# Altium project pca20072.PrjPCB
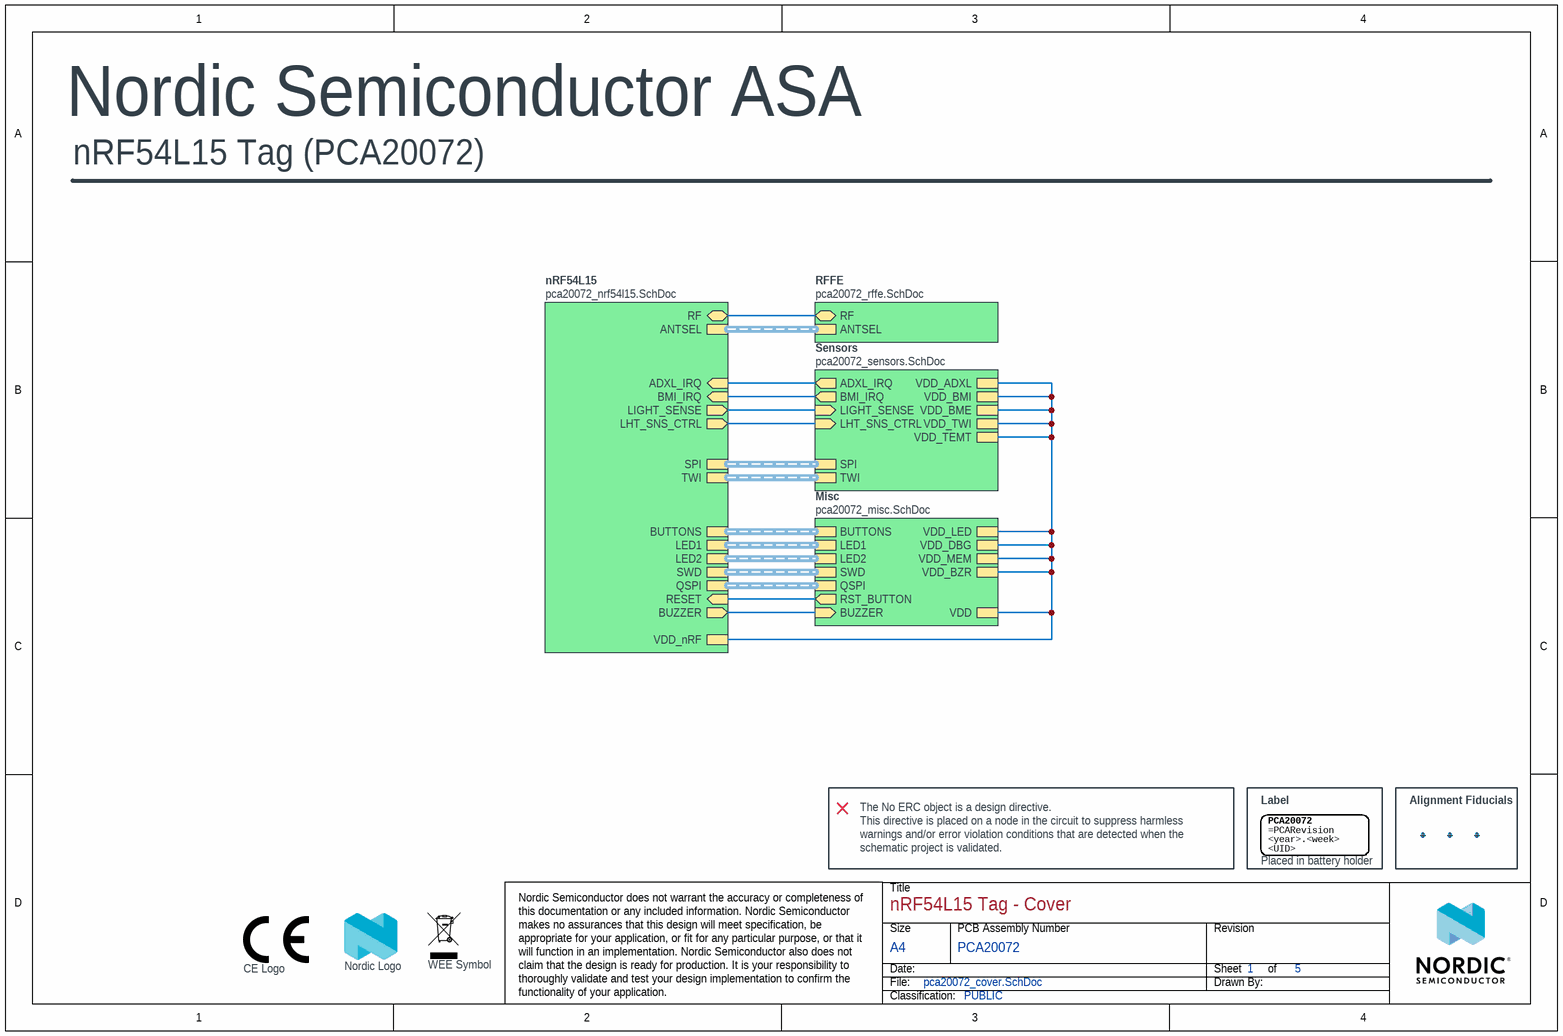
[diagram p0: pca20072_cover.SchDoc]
BoardThickness: 0.8mm; BoardTitle: nRF54L15 Tag; Classification: PUBLIC; Compliance: RoHS, REACH, Halogen-Free; Designer: RUBR; Dielectric: FR-4; NrOfLayers: 4; Organization: Nordic Semiconductor; PCAName: PCA20072; PCARevision: 1.0.0; PCBNumber: 400921; PCBRevision: 0491RUBR; PCBStackup: 4003; ProductName: nRF54L15-TAG; ProjectName: nRF54L15-TAG; SilkscreenColor: White; SoldermaskColor: Blue; SurfaceFinish: ENIG Gold
5 sheets, 113 parts. Net scope: hierarchical (ports join the sheet entries above them; power ports are global).
Board file: 400921.PcbDoc
Sheets:
  pca20072_cover.SchDoc
    nRF54L15 = pca20072_nrf54l15.SchDoc
    RFFE = pca20072_rffe.SchDoc
    Sensors = pca20072_sensors.SchDoc
    Misc = pca20072_misc.SchDoc

## Sheet pca20072_cover.SchDoc: nRF54L15 Tag - Cover
size A4; Organization: Nordic Semiconductor; DocumentNumber: 1; Revision: 1.0.0; SheetNumber: 1; SheetTotal: 5; Author: RUBR; CompanyName: Nordic Semiconductor; DrawnBy: RUBR; DocumentSize: A4

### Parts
Fid1  Fiducial mark  [Fiducial]  (value not drawn)
Fid2  Fiducial mark  [Fiducial]  (value not drawn)
Fid3  Fiducial mark  [Fiducial]  (value not drawn)
LABEL1  Assembly: Placed in battery holder  [LabelSilk_8x8]  (hidden comment: 8x8mm)
LOGO1  WEE Symbol  [WEEE_3x4.5mm]  (no BOM)
LOGO2  Nordic Logo  [NORDIC_LOGO_LYING]  (no BOM)
LOGO3  CE Logo  [CE_logo]  (no BOM)

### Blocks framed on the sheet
Label: LABEL1
Alignment Fiducials: Fid1-Fid3

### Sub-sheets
Misc = pca20072_misc.SchDoc: BUTTONS (harness BUTTON), QSPI (harness QSPI), LED1 (harness LED), SWD (harness SWD), VDD_MEM, VDD_LED, VDD_DBG, LED2 (harness LED), BUZZER (in), VDD_BZR, RST_BUTTON (out), VDD
nRF54L15 = pca20072_nrf54l15.SchDoc: BUTTONS (harness BUTTON), LED1 (harness LED), SWD (harness SWD), RESET (in), RF (bidir), ANTSEL (harness ANT), QSPI (harness QSPI), ADXL_IRQ (in), BMI_IRQ (in), SPI (harness SPI), TWI (harness TWI), VDD_nRF, LHT_SNS_CTRL (out), LED2 (harness LED), LIGHT_SENSE (out), BUZZER (out)
RFFE = pca20072_rffe.SchDoc: RF (bidir), ANTSEL (harness ANT)
Sensors = pca20072_sensors.SchDoc: ADXL_IRQ (out), BMI_IRQ (out), SPI (harness SPI), TWI (harness TWI), VDD_BMI, VDD_ADXL, VDD_BME, VDD_TWI, LIGHT_SENSE (in), LHT_SNS_CTRL (in), VDD_TEMT

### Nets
P0.03: sheet nRF54L15/ADXL_IRQ, sheet Sensors/ADXL_IRQ
P1.04: sheet nRF54L15/BMI_IRQ, sheet Sensors/BMI_IRQ
P1.13: sheet nRF54L15/BUZZER, sheet Misc/BUZZER
P1.14: sheet nRF54L15/LIGHT_SENSE, sheet Sensors/LIGHT_SENSE
P2.06: sheet nRF54L15/LHT_SNS_CTRL, sheet Sensors/LHT_SNS_CTRL
RESET: sheet nRF54L15/RESET, sheet Misc/RST_BUTTON
RF: sheet nRF54L15/RF, sheet RFFE/RF
VDD: sheet nRF54L15/VDD_nRF, sheet Sensors/VDD_BMI, sheet Sensors/VDD_ADXL, sheet Sensors/VDD_BME, sheet Sensors/VDD_TWI, sheet Sensors/VDD_TEMT, sheet Misc/VDD_MEM, sheet Misc/VDD_LED, sheet Misc/VDD_DBG, sheet Misc/VDD_BZR, sheet Misc/VDD

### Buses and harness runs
harness sheet Misc/BUTTONS = sheet nRF54L15/BUTTONS
harness sheet Misc/LED1 = sheet nRF54L15/LED1
harness sheet Misc/LED2 = sheet nRF54L15/LED2
harness sheet Misc/QSPI = sheet nRF54L15/QSPI
harness sheet Misc/SWD = sheet nRF54L15/SWD
harness sheet nRF54L15/ANTSEL = sheet RFFE/ANTSEL
harness sheet nRF54L15/SPI = sheet Sensors/SPI
harness sheet nRF54L15/TWI = sheet Sensors/TWI

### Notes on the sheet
- (near LABEL1) The No ERC object is a design directive.
  This directive is placed on a node in the circuit to suppress harmless warnings and/or error violation conditions that are detected when the schematic project is validated.

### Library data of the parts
Fid1-Fid3 = Fid-Mark: Manufacturer: N.A.; Part number NEMS: 100500073; Value: N.A.; Pad Count: 1; Component Status: Active; System: Connector
LABEL1 = Label_8x8: PCA version label, stick-on, 8x8mm; Manufacturer: Ellco Etikett; Manufacturer Part Number: A33511-01; Part number NEMS: 101200025; Component Status: Active; Pad Count: 0; Note: N.A.
LOGO1 = WEEE Symbol 3x4.5mm: WEEE Directive symbol; Manufacturer: N.A.; Part number NEMS: 101100006; Component Status: Active; Pad Count: 0
LOGO2 = Nordic Logo lying: Manufacturer: N.A.; Part number NEMS: 101100001; Component Status: Active; Pad Count: 0
LOGO3 = CE_logo: CE (Conformité_Européenne) logo; Manufacturer: N.A.; Part number NEMS: 101100010; Component Status: Active; Pad Count: 0

## Sheet pca20072_nrf54l15.SchDoc: =BoardTitle+' - nRF54L15'
size A4; Organization: Nordic Semiconductor; DocumentNumber: 2; Revision: 1.0.0; SheetNumber: 2; SheetTotal: 5; Author: RUBR; CompanyName: Nordic Semiconductor; DrawnBy: RUBR; DocumentSize: A4
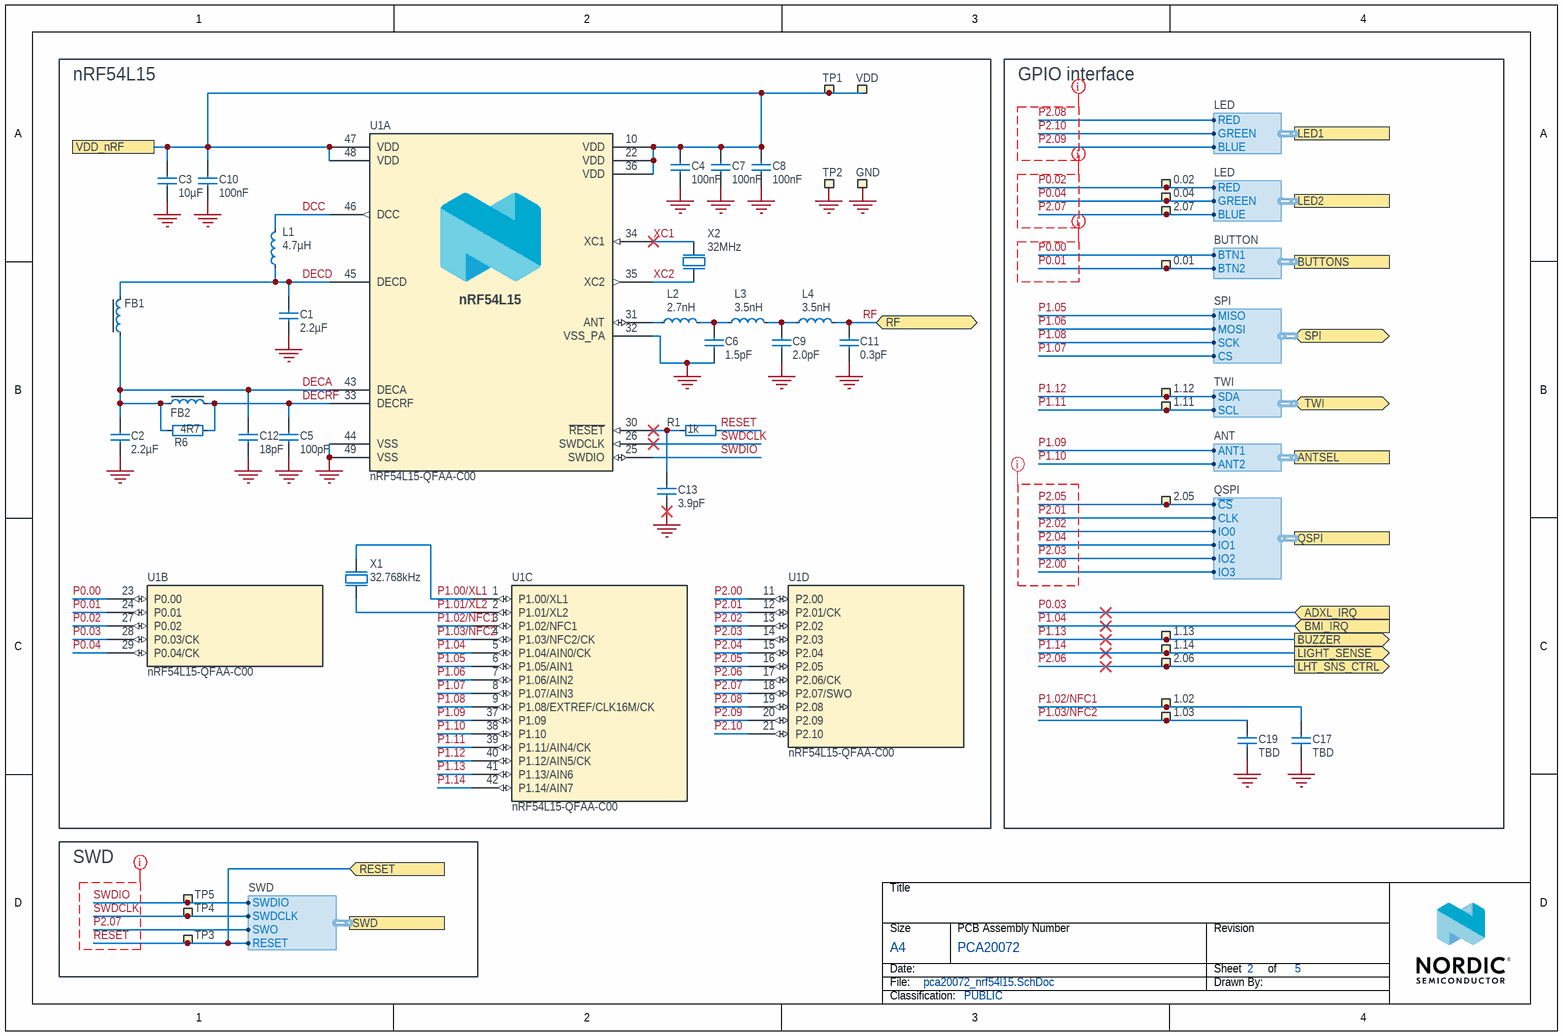
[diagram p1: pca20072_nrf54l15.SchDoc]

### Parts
0.01  TP  [TESTPAD-TH]  (value not drawn)  (no BOM)
0.02  TP  [TESTPAD-TH]  (value not drawn)  (no BOM)
0.04  TP  [TESTPAD-TH]  (value not drawn)  (no BOM)
1.02  TP  [TESTPAD-TH]  (value not drawn)  (no BOM)
1.03  TP  [TESTPAD-TH]  (value not drawn)  (no BOM)
1.11  TP  [TESTPAD-TH]  (value not drawn)  (no BOM)
1.12  TP  [TESTPAD-TH]  (value not drawn)  (no BOM)
1.13  TP  [TESTPAD-TH]  (value not drawn)  (no BOM)
1.14  TP  [TESTPAD-TH]  (value not drawn)  (no BOM)
2.05  TP  [TESTPAD-TH]  (value not drawn)  (no BOM)
2.06  TP  [TESTPAD-TH]  (value not drawn)  (no BOM)
2.07  TP  [TESTPAD-TH]  (value not drawn)  (no BOM)
C1  2.2µF  [CAPC0603X03L_C]
C2  2.2µF  [CAPC0603X03L_C]
C3  10µF  [CAPC1005X04L_C2]
C4  100nF  [CAPC0603X03L_C]
C5  100pF  [CAPC0603X03L_C]
C6  1.5pF  [CAPC0603X03L_C]
C7  100nF  [CAPC0603X03L_C]
C8  100nF  [CAPC0603X03L_C]
C9  2.0pF  [CAPC0603X03L_C]
C10  100nF  [CAPC0603X03L_C]
C11  0.3pF  [CAPC0603X03L_C]
C12  18pF  [CAPC0603X03L_C]
C13  3.9pF  [CAPC0603X03L_C]
C17  TBD  [CAPC1005X04L]
C19  TBD  [CAPC1005X04L]
FB1  120R/0.2A  [INDC0603X03L_C]  (value not drawn)
FB2  120R/0.2A  [INDC0603X03L_C]  (value not drawn)
GND  TP  [TESTPAD-TH]  (value not drawn)  (no BOM)
L1  4.7µH  [INDC1608X06L]
L2  2.7nH  [INDC0603X03L_C]
L3  3.5nH  [INDC0603X03L_C]
L4  3.5nH  [INDC0603X03L_C]
R1  1k  [RESC0603X03L_C]
R6  4R7  [RESC0603X03L_C]
TP1  Ø1.5mm,SMD  [TP_SMD_D1.5mm]  (value not drawn)  (no BOM)
TP2  Ø1.5mm,SMD  [TP_SMD_D1.5mm]  (value not drawn)  (no BOM)
TP3  Ø1.5mm,SMD  [TP_SMD_D1.5mm]  (value not drawn)  (no BOM)
TP4  Ø1.5mm,SMD  [TP_SMD_D1.5mm]  (value not drawn)  (no BOM)
TP5  Ø1.5mm,SMD  [TP_SMD_D1.5mm]  (value not drawn)  (no BOM)
U1  nRF54L15-QFAA-C00  [QFN40P600X600X90-48N]  (parts A,B,C,D of 4)
VDD  TP  [TESTPAD-TH]  (value not drawn)  (no BOM)
X1  32.768kHz  [XTAL_2012]
X2  32MHz  [BT-XTAL_2016]

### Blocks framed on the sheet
nRF54L15: C1-C13 FB1 FB2 GND L1-L4 R1 R6 TP1 TP2 U1 VDD X1 X2
GPIO interface: 0.01 0.02 0.04 1.02 1.03 1.11-1.14 2.05 2.06 2.07 C17 C19
SWD: TP3-TP5

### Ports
ADXL_IRQ (in), ANTSEL (harness ANT), BMI_IRQ (in), BUTTONS (harness BUTTON), BUZZER (out), LED1 (harness LED), LED2 (harness LED), LHT_SNS_CTRL (out), LIGHT_SENSE (out), QSPI (harness QSPI), RESET (in), RF (bidir), SPI (bidir, harness SPI), SWD (harness SWD), TWI (bidir, harness TWI), VDD_nRF

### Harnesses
SWD: SWDIO, SWDCLK, SWO, RESET
LED: GREEN, RED, BLUE
BUTTON: BTN2, BTN1
ANT: ANT2, ANT1
QSPI: ~{CS}, IO0, CLK, IO1, IO2, IO3
SPI: MISO, MOSI, SCK, CS
TWI: SCL, SDA

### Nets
GND: C1.1 C2.1 C3.1 C4.2 C5.1 C6.1 C7.2 C8.2 C9.1 C10.2 C11.1 C12.1 C13.1 C17.2 C19.2 GND.1 TP2.1 U1.32(VSS_PA) U1.44(VSS) U1.49(VSS) X2.2(GND) X2.4(GND)
DCC: L1.1 U1.46(DCC)
DECA: C2.2 C12.2 FB1.2 FB2.2 R6.2 U1.43(DECA)
DECD: C1.2 FB1.1 L1.2 U1.45(DECD)
DECRF: C5.2 FB2.1 R6.1 U1.33(DECRF)
P0.00: U1.23(P0.00) ; port BUTTONS.BTN1
P0.01: 0.01.1 U1.24(P0.01) ; port BUTTONS.BTN2
P0.02: 0.02.1 U1.27(P0.02) ; port LED2.RED
P0.03: U1.28(P0.03/CK) ; port ADXL_IRQ
P0.04: 0.04.1 U1.29(P0.04/CK) ; port LED2.GREEN
P1.00/XL1: U1.1(P1.00/XL1) X1.2(out)
P1.01/XL2: U1.2(P1.01/XL2) X1.1(inp)
P1.02/NFC1: 1.02.1 C17.1 U1.3(P1.02/NFC1)
P1.03/NFC2: 1.03.1 C19.1 U1.4(P1.03/NFC2/CK)
P1.04: U1.5(P1.04/AIN0/CK) ; port BMI_IRQ
P1.05: U1.6(P1.05/AIN1) ; port SPI.MISO
P1.06: U1.7(P1.06/AIN2) ; port SPI.MOSI
P1.07: U1.8(P1.07/AIN3) ; port SPI.CS
P1.08: U1.9(P1.08/EXTREF/CLK16M/CK) ; port SPI.SCK
P1.09: U1.37(P1.09) ; port ANTSEL.ANT1
P1.10: U1.38(P1.10) ; port ANTSEL.ANT2
P1.11: 1.11.1 U1.39(P1.11/AIN4/CK) ; port TWI.SCL
P1.12: 1.12.1 U1.40(P1.12/AIN5/CK) ; port TWI.SDA
P1.13: 1.13.1 U1.41(P1.13/AIN6) ; port BUZZER
P1.14: 1.14.1 U1.42(P1.14/AIN7) ; port LIGHT_SENSE
P2.00: U1.11(P2.00) ; port QSPI.IO3
P2.01: U1.12(P2.01/CK) ; port QSPI.CLK
P2.02: U1.13(P2.02) ; port QSPI.IO0
P2.03: U1.14(P2.03) ; port QSPI.IO2
P2.04: U1.15(P2.04) ; port QSPI.IO1
P2.05: 2.05.1 U1.16(P2.05) ; port QSPI.~{CS}
P2.06: 2.06.1 U1.17(P2.06/CK) ; port LHT_SNS_CTRL
P2.07: 2.07.1 U1.18(P2.07/SWO) ; port SWD.SWO, port LED2.BLUE
P2.08: U1.19(P2.08) ; port LED1.RED
P2.09: U1.20(P2.09) ; port LED1.BLUE
P2.10: U1.21(P2.10) ; port LED1.GREEN
RESET: R1.2 TP3.1 ; port RESET, port SWD.RESET
RF: C11.2 L4.2 ; port RF
SWDCLK: TP4.1 U1.26(SWDCLK) ; port SWD.SWDCLK
SWDIO: TP5.1 U1.25(SWDIO) ; port SWD.SWDIO
VDD: C3.2 C4.1 C7.1 C8.1 C10.1 TP1.1 U1.10(VDD) U1.22(VDD) U1.36(VDD) U1.47(VDD) U1.48(VDD) VDD.1 ; port VDD_nRF
XC1: U1.34(XC1) X2.1(inp)
XC2: U1.35(XC2) X2.3(out)
NetC6_2: C6.2 L2.2 L3.1
NetC9_2: C9.2 L3.2 L4.1
NetC13_2: C13.2 R1.1 U1.30(~{RESET})
NetL2_1: L2.1 U1.31(ANT)

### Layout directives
net class GPIO: P0.00, P0.01, P0.02, P0.04, P2.07, P2.08, P2.09, P2.10
net class SWD_nRF54: P2.07, RESET, SWDCLK, SWDIO
net class QSPI: P2.00, P2.01, P2.02, P2.03, P2.04, P2.05

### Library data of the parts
0.01 0.02 0.04 1.02 1.03 1.11-1.14 2.05 2.06 2.07 GND VDD = Testpoint TH: Testpoint, through hole; Manufacturer: N.A.; Part number NEMS: 100500464; Component Status: Active; Pad Count: 1
C1 C2 = C0201-2µ2-2.5V-X6T-GRM033D80E225ME47D: Capacitor, Ceramic, 2.2µF 2.5V X6T 0201,±20%; Manufacturer: Murata; Part number NEMS: 100200527; Component Status: Active; Pad Count: 2; Note: 2.5V, 20%, X6T; Artikkelnr Noca: N.A.
C3 = C0402-10µ-6.3V-X5R-GRM155R60J106ME05D: Capacitor, X5R, ±20%, 6.3V; Manufacturer: Murata; Part number NEMS: 100200554; Component Status: Active; Pad Count: 2; Artikkelnr Noca: N.A.
C4 C7 C8 C10 = C0201-100n: Capacitor, X5R, ±10%, 100nF, 16V; Manufacturer: N.A.; Part number IPS: 00000001248, 00000002505; Part number Norautron: 262071862; Part number NEMS: 100200078; Pad Count: 2; Component Status: Active
C5 = C0201-100p: Capacitor, NP0, ±2%, 25V; Manufacturer: Murata; Manufacturer Part Number: GRM0335C1E101GA01D; Part number IPS: 00000007853; Part number NEMS: 100200044; Component Status: Active; Pad Count: 2; Artikkelnr Noca: N.A.
C6 = C0201-1.5p-25V-NP0-GJM0335C1E1R5WB01: Capacitor, NP0, ±0.05pF, 25V, High Q; Manufacturer: Murata; Part number NEMS: 100200477; Component Status: Active; Pad Count: 2; Artikkelnr Noca: N.A.
C9 = C0201-2.0p-HQ-Murata: Capacitor, NP0, ±0.05pF, 25V; Manufacturer: Murata; Manufacturer Part Number: GJM0335C1E2R0WB01; Part number IPS: 00000001775; Part number NEMS: 100200419; Component Status: Active; Pad Count: 2; Artikkelnr Noca: N.A.
C11 = C0201-0.3p-50V-GRM0335C1HR30BA01: Capacitor, C0G, ±0.1pF, 50V; Manufacturer: Murata; Part number NEMS: 100200650; Component Status: Active; Pad Count: 2; Artikkelnr Noca: N.A.
C12 = C0201-18p: Capacitor, C0G, ±5%, 25V; Manufacturer: Walsin Technology Corporation; Manufacturer Part Number: 0201N180J250CT; Part number IPS: 00000000862; Part number Norautron: 26207023; Part number NEMS: 100200035; Component Status: Active; Pad Count: 2; Note: Chip Cap 5%; Artikkelnr Noca: N.A.
C13 = C0201-3.9p: Chip Cap 0201; Manufacturer: N.A.; Part number NEMS: 100200024,100200424; Component Status: Active; Pad Count: 2; Note: Chip Cap 1%
C17 C19 = C0402-TBD: Chip Cap 0402; Manufacturer: N.A.; Part number NEMS: 100200106; Pad Count: 2; Component Status: Active
FB1 FB2 = FB0201-120R@100M-200mA-BLM03AG121SN1D: Ferrite Bead, 120 Ohm @ 100MHz, 200mA, 500 mOhm Max; Manufacturer: Murata; Part number NEMS: 100300419; Component Status: Active; Pad Count: 2; Artikkelnr Noca: N.A.
L1 = L0603-4µ7-MLZ1608M4R7WT000: Inductor, 120mA, ±20%, 0.65R; Manufacturer: TDK Corporation; Part number NEMS: 100300440; Component Status: Active; Pad Count: 2; Note: Power Inductor ±20%; Artikkelnr Noca: N.A.
L2 = L0201-2n7-HQ-Murata: Inductor, 600mA, ±0.1ｎH, 120mOhm; Manufacturer: Murata; Manufacturer Part Number: LQP03HQ2N7B02; Part number IPS: 00000001753; Part number NEMS: 100300214; Component Status: Active; Pad Count: 2; Note: -55°C ~ 125°C; Artikkelnr Noca: N.A.
L3 L4 = L0201-3n5-HQ-Murata: Inductor, 500mA, ±0.1ｎH, 170mOhm; Manufacturer: Murata; Manufacturer Part Number: LQP03HQ3N5B02; Part number NEMS: 100300222; Component Status: Active; Pad Count: 2; Note: -55°C ~ 125°C; Artikkelnr Noca: N.A.
R1 = R0201-1k0: Resistor, ±1%, 0.05W; Manufacturer: N.A.; Part number IPS: 00000005786; Part number NEMS: 100100043; Component Status: Active; Pad Count: 2; Note: Chip Res 1%
R6 = R0201-4R7: Resistor, ±1%, 0.05W; Manufacturer: N.A.; Part number IPS: 00000002486; Part number NEMS: 100100010; Component Status: Active; Pad Count: 2; Note: Chip Res 1%
TP1-TP5 = TP_SMD_Ø1.5MM: 1.5mm circular SMD testpad; Manufacturer: Nordic Semiconductor; Manufacturer Part Number: N.A.; Part number NEMS: 100500477; Component Status: Active; Pad Count: 1
U1 = nRF54L15-QFAA-C00: Multi-protocol Bluetooth Low Energy, IEEE 802.15.4 and 2.4GHz proprietary Wireless MCU; Manufacturer: Nordic Semiconductor; Part number NEMS: 102000382; Component Status: Active; Pad Count: 49; Note: N.A.
X1 = XTAL_SMD2012_32.768kHz_9pF_TXC: XTAL SMD 2012, 32.768kHz, 9pF, ±20ppm; Manufacturer: TXC Corporation; Manufacturer Part Number: 9HT11-32.768KDZC-T; Part number NEMS: 101600107; Component Status: Active; Pad Count: 2; Note: XTAL SMD 32.768kHz; Artikkelnr Noca: N.A.
X2 = XTAL_SMD2016_32MHz_8pF_Kyocera: XTAL SMD 2016, 32MHz, Cl=8pF, Tot: ±40ppm; Manufacturer Part Number: CX2016DB32000D0WZRC1; Part number IPS: 00000007827; Part number Norautron: 26511136; Part number NEMS: 101600039; Component Status: Active; Pad Count: 4; Note: XTAL SMD 32.000MHz; Artikkelnr Noca: 22010022

## Sheet pca20072_rffe.SchDoc: nRF54L15 Tag - RFFE
size A4; Organization: Nordic Semiconductor; DocumentNumber: 3; Revision: 1.0.0; SheetNumber: 3; SheetTotal: 5; Author: RUBR; CompanyName: Nordic Semiconductor; DrawnBy: RUBR; DocumentSize: A4
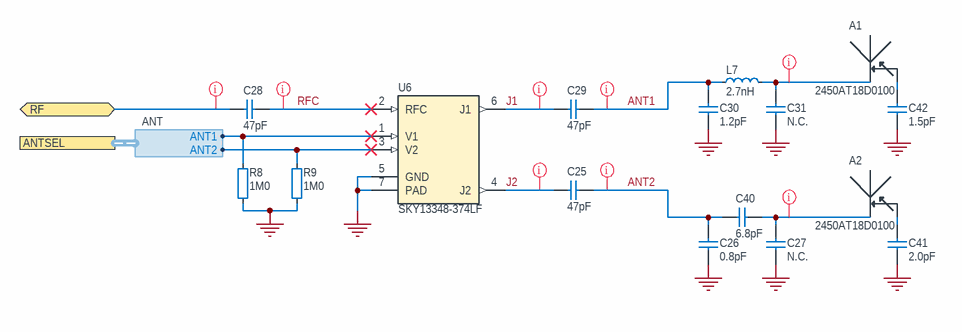
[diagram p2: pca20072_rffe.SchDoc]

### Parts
A1  2450AT18D0100  [2450AT18D0100_TE-R]
A2  2450AT18D0100  [2450AT18D0100_TE-L]
C25  47pF  [CAPC0603X03L_C]
C26  0.8pF  [CAPC1005X04L_C2]
C27  N.C.  [CAPC1005X04L_C2]
C28  47pF  [CAPC0603X03L_C]
C29  47pF  [CAPC0603X03L_C]
C30  1.2pF  [CAPC1005X04L_C2]
C31  N.C.  [CAPC1005X04L_C2]
C40  6.8pF  [CAPC1005X04L_C2]
C41  2.0pF  [CAPC1005X04L_C2]
C42  1.5pF  [CAPC1005X04L_C2]
L7  2.7nH  [INDC1005X04L_C2]
R8  1M0  [RESC0603X03L_C]
R9  1M0  [RESC0603X03L_C]
U6  SKY13348-374LF  [SON50P150X50_HS-7N]

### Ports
ANTSEL (harness ANT), RF (bidir)

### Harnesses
ANT: ANT2, ANT1

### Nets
GND: A1.2(GND) A2.2(GND) C26.1 C27.1 C30.1 C31.1 C41.1 C42.1 R8.1 R9.1 U6.5(GND) U6.7(PAD)
ANT1: C29.1 C30.2 L7.1
ANT2: C25.1 C26.2 C40.1
J1: C29.2 U6.6(J1)
J2: C25.2 U6.4(J2)
P1.09: R8.2 U6.1(V1) ; port ANTSEL.ANT1
P1.10: R9.2 U6.3(V2) ; port ANTSEL.ANT2
RF: C28.2 ; port RF
RFC: C28.1 U6.2(RFC)
NetA1_1: A1.1 C31.2 L7.2
NetA1_3: A1.3(Tuning) C42.2
NetA2_1: A2.1 C27.2 C40.2
NetA2_3: A2.3(Tuning) C41.2

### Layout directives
net class RF: ANT1, ANT2, J1, J2, NetA1_1, NetA2_1, RF, RFC

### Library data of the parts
A1 A2 = Johanson 2450AT18D0100_TE: 2.45 GHz chip antenna; Manufacturer: Johanson Technology; Part number IPS: 00000001415; Part number NEMS: 100700004, 100700005, 100700006; Component Status: Active; Pad Count: 4; Note: N.A.; Artikkelnr Noca: 53059035
C25 C28 C29 = C0201-47p-25V-NP0-QLCD250Q470G1GV001T: Capacitor, High Q, Low Loss, C0G/NP0, 25V, ±2%, -55°C ~ 125°C; Manufacturer: Johanson Technology; Part number IPS: 00000010810; Component Status: Active; Pad Count: 2; Artikkelnr Noca: N.A.
C26 = C0402-0.8p: Capacitor, NP0, ±5%; Manufacturer: Murata; Manufacturer Part Number: GRM1555C1HR80WA01D; Part number IPS: 00000007782; Part number Norautron: N.A.; Part number NEMS: 100200116; Component Status: Active; Pad Count: 2; Note: 50V; Artikkelnr Noca: 20029147
C27 C31 = C0402-N.C.: Not mounted; Manufacturer: N.A.; Part number NEMS: 100200105; Component Status: Active; Pad Count: 2; Note: Chip Cap; Assembly: Not mounted
C30 = C0402-1.2p: Capacitor, NP0, ±0.1pF; Manufacturer: N.A.; Part number IPS: 00000005410; Part number NEMS: 100200119; Component Status: Active; Pad Count: 2; Note: 50V; Artikkelnr Noca: 20029157
C40 = C0402-6.8p-50V-NP0-GJM1555C1H6R8BB01D: Capacitor, High Q, Low Loss, C0G/NP0, 50V, ±0.1pF, -55°C ~ 125°C; Manufacturer: Murata; Part number IPS: 80000004966; Component Status: Active; Pad Count: 2; Artikkelnr Noca: N.A.
C41 = C0402-2.0p-50V-NP0-GJM1555C1H2R0BB01: Capacitor, High Q, Low Loss, C0G/NP0, 50V, ±0.1pF, -55°C ~ 125°C; Manufacturer: Murata; Part number IPS: 80000004957; Part number NEMS: 100200697; Component Status: Active; Pad Count: 2; Artikkelnr Noca: N.A.
C42 = C0402-1.5p-50V-NP0-GJM1555C1H1R5BB01D: Capacitor, High Q, Low Loss, C0G/NP0, 50V, ±0.1pF, -55°C ~ 125°C; Manufacturer: Murata; Part number IPS: 80000004967; Component Status: Active; Pad Count: 2; Artikkelnr Noca: N.A.
L7 = L0402-2n7-Multilayer_Murata: Inductor, 800mA, ±2%, 120mΩ; Manufacturer: Murata; Manufacturer Part Number: LQG15HS2N7B02D; Part number NEMS: 100300445; Component Status: Active; Pad Count: 2; Note: -55°C ~ 125°C; Artikkelnr Noca: N.A.
R8 R9 = R0201-1M0: Resistor, ±1%, 0.05W; Manufacturer: N.A.; Part number IPS: 00000001418; Part number Norautron: 26107108; Part number NEMS: 100100093; Component Status: Active; Pad Count: 2; Note: Chip Res 1%
U6 = SKY13348-374LF: 50 MHz-6.0 GHz GaAs SPDT Switch; Manufacturer: Skyworks; Part number NEMS: 101900872; Component Status: Active; Pad Count: 6; Note: N.A.

## Sheet pca20072_sensors.SchDoc: nRF54L15 Tag - Sensors
size A4; Organization: Nordic Semiconductor; DocumentNumber: 4; Revision: 1.0.0; SheetNumber: 4; SheetTotal: 5; Author: RUBR; CompanyName: Nordic Semiconductor; DrawnBy: RUBR; DocumentSize: A4
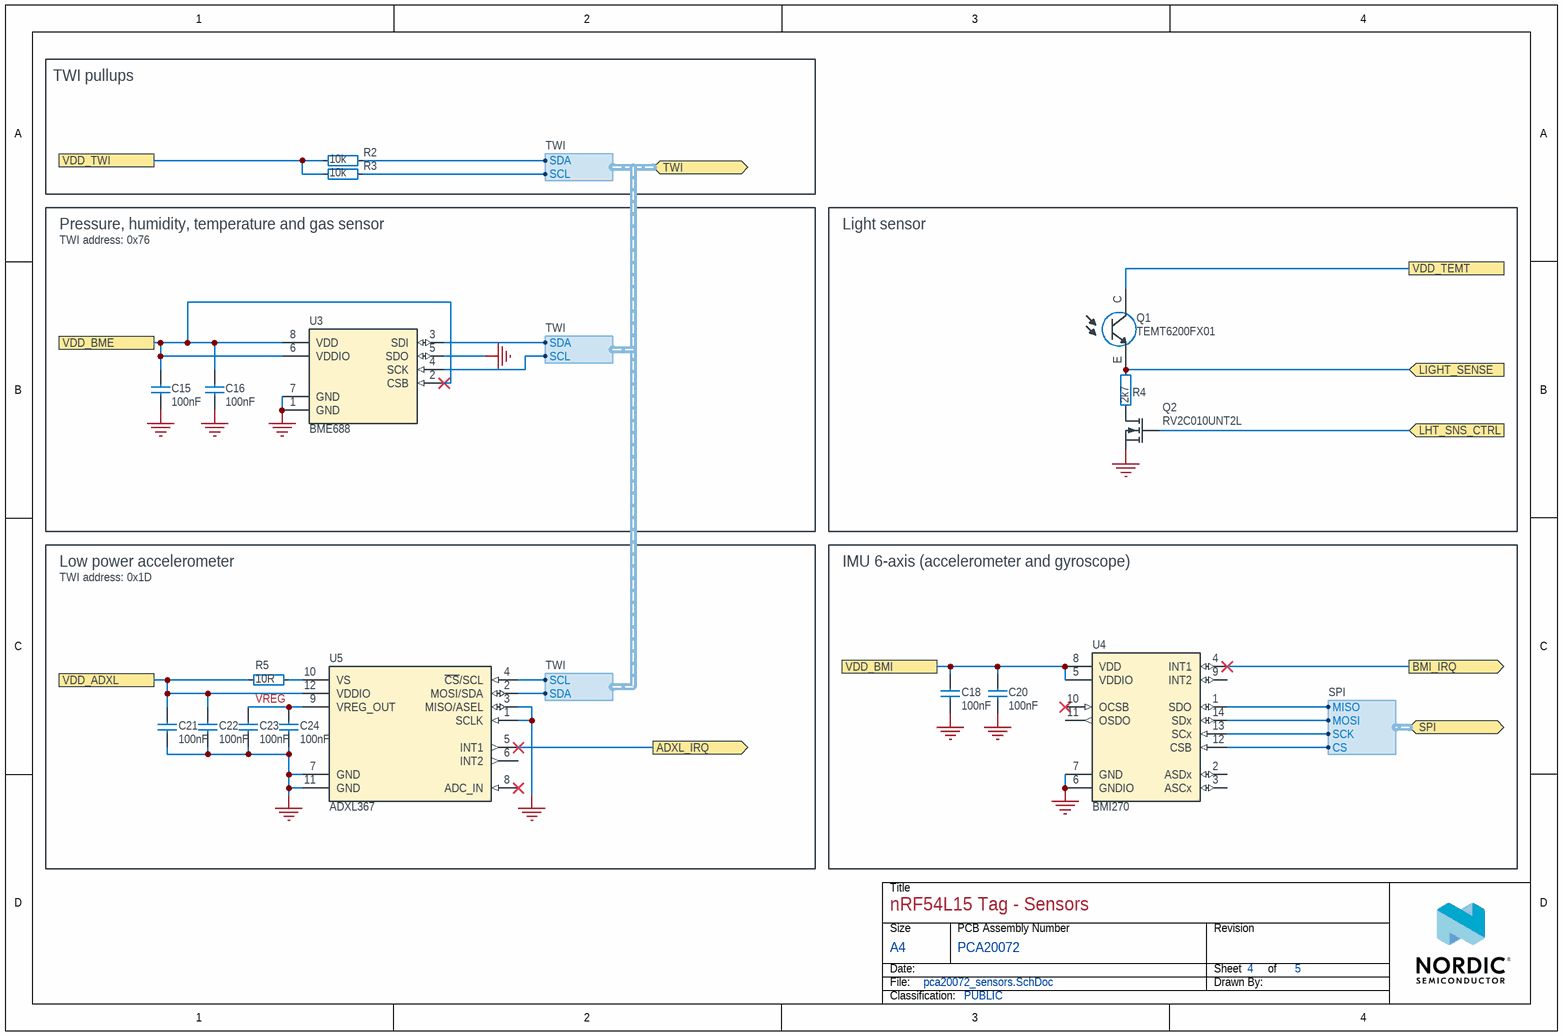
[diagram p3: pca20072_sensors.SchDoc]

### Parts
C15  100nF  [CAPC0603X03L_C]
C16  100nF  [CAPC0603X03L_C]
C18  100nF  [CAPC0603X03L_C]
C20  100nF  [CAPC0603X03L_C]
C21  100nF  [CAPC0603X03L_C]
C22  100nF  [CAPC0603X03L_C]
C23  100nF  [CAPC0603X03L_C]
C24  100nF  [CAPC0603X03L_C]
Q1  TEMT6200FX01  [TEMT6200FX01]
Q2  RV2C010UNT2L  [DFN65P100X40-3L]
R2  10k  [RESC0603X03L_C]
R3  10k  [RESC0603X03L_C]
R4  2k7  [RESC0603X03L_C]
R5  10R  [RESC0603X03L_C]
U3  BME688  [BME680]
U4  BMI270  [BMI270]
U5  ADXL367  [LGA50P220X230X97-12N]

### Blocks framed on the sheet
TWI pullups: R2 R3
Pressure, humidity, temperature and gas sensor: C15 C16 U3
Light sensor: Q1 Q2 R4
Low power accelerometer: C21-C24 R5 U5
IMU 6-axis (accelerometer and gyroscope): C18 C20 U4

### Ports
ADXL_IRQ (out), BMI_IRQ (out), LHT_SNS_CTRL (in), LIGHT_SENSE (in), SPI (bidir, harness SPI), TWI (bidir, harness TWI), VDD_ADXL, VDD_BME, VDD_BMI, VDD_TEMT, VDD_TWI

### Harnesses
TWI: SCL, SDA
SPI: MISO, MOSI, SCK, CS

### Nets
GND: C15.1 C16.1 C18.1 C20.1 C21.1 C22.1 C23.1 C24.1 Q2.2(S) U3.1(GND) U3.5(SDO) U3.7(GND) U4.6(GNDIO) U4.7(GND) U5.1(SCLK) U5.3(MISO/ASEL) U5.7(GND) U5.11(GND)
P0.03: U5.5(INT1) ; port ADXL_IRQ
P1.04: U4.4(INT1) ; port BMI_IRQ
P1.05: U4.1(SDO) ; port SPI.MISO
P1.06: U4.14(SDx) ; port SPI.MOSI
P1.07: U4.12(CSB) ; port SPI.CS
P1.08: U4.13(SCx) ; port SPI.SCK
P1.11: R3.1 U3.4(SCK) U5.4(~{CS}/SCL) ; port TWI.SCL
P1.12: R2.1 U3.3(SDI) U5.2(MOSI/SDA) ; port TWI.SDA
P1.14: Q1.E R4.2 ; port LIGHT_SENSE
P2.06: Q2.1(G) ; port LHT_SNS_CTRL
VDD: C15.2 C16.2 C18.2 C20.2 C21.2 C22.2 Q1.C R2.2 R3.2 R5.1 U3.2(CSB) U3.6(VDDIO) U3.8(VDD) U4.5(VDDIO) U4.8(VDD) U5.12(VDDIO) ; port VDD_BMI, port VDD_ADXL, port VDD_BME, port VDD_TWI, port VDD_TEMT
VREG: C23.2 C24.2 U5.9(VREG_OUT)
NetQ2_3: Q2.3(D) R4.1
NetR5_2: R5.2 U5.10(VS)

Not connected (* = marked no-connect by the designer): U4 2(ASDx) 3(ASCx) 9(INT2) 10(OCSB)* 11(OSDO); U5 6(INT2) 8(ADC_IN)*

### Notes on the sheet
- TWI address: 0x76
- TWI address: 0x1D

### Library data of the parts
C15 C16 C21-C24 = C0201-100n: Capacitor, X5R, ±10%, 100nF, 16V; Manufacturer: N.A.; Part number IPS: 00000001248, 00000002505; Part number Norautron: 262071862; Part number NEMS: 100200078; Component Status: Active; Pad Count: 2
C18 C20 = C0201-100n: as C4 on sheet pca20072_nrf54l15
Q1 = TEMT6200FX01: Phototransistors 550nm Top View 0805 (2012 Metric); Manufacturer: Vishay; Part number NEMS: 101400145; Component Status: Active; Pad Count: 2; Note: N.A.
Q2 = RV2C010UNT2L: N-Channel MOSFET, 20V, 1A, 470mOhm, 400mW, -55°C ~ 150°C; Manufacturer: Rohm Semiconductor; Part number IPS: 00000009976; Part number Norautron: 26320026; Part number NEMS: 101300132; Component Status: Active; Pad Count: 3; Note: N.A.; Artikkelnr Noca: 35010020
R2 R3 = R0201-10k: Resistor, ±1%, 0.05W; Manufacturer: N.A.; Part number IPS: 00000001255; Part number Norautron: 26107101; Part number NEMS: 100100065; Component Status: Active; Pad Count: 2; Note: Chip Res 1%
R4 = R0201-2k7: Resistor, ±1%, 0.05W; Manufacturer: N.A.; Part number Norautron: 26108481; Part number NEMS: 100100054; Component Status: Active; Pad Count: 2; Note: Chip Res 1%
R5 = R0201-10R: Resistor, ±1%, 0.05W; Manufacturer: N.A.; Part number NEMS: 100100014; Component Status: Active; Pad Count: 2; Note: Chip Res 1%
U3 = BME688: Low power gas, pressure, temperature & humidity sensor; Manufacturer: Bosch; Part number NEMS: 101900619; Component Status: Active; Pad Count: 8; Note: N.A.
U4 = BMI270: 6-axis, smart, low-power, inertial measurement unit; Manufacturer: Bosch; Part number NEMS: 101900620; Note: N.A.; Pad Count: 14; Component Status: Active
U5 = ADXL367BCCZ: Micropower, 3-Axis, ±2 g/±4 g/±8 g Digital Output MEMS Accelerometer; Manufacturer: Analog Devices; Part number NEMS: 101900775; Note: N.A.; Component Status: Active; Pad Count: 12

## Sheet pca20072_misc.SchDoc: =BoardTitle+' - Misc'
size A4; Organization: Nordic Semiconductor; DocumentNumber: 5; Revision: 1.0.0; SheetNumber: 5; SheetTotal: 5; Author: RUBR; CompanyName: Nordic Semiconductor; DrawnBy: RUBR; DocumentSize: A4
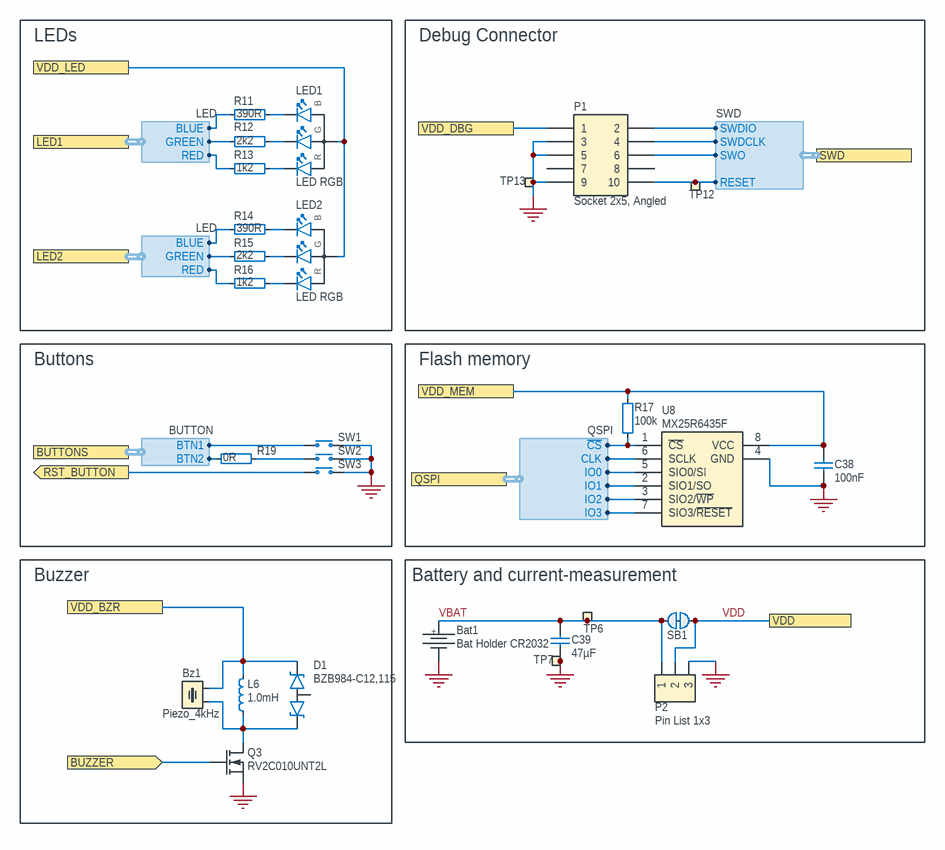
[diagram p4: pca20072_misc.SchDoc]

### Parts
Bat1  Bat Holder CR2032  [L-KLS5-CR2032-23-B1]
Bz1  Piezo_4kHz  [Buzzer_PKMCS0909]
C38  100nF  [CAPC0603X03L_C]
C39  47µF  [CAPC1608X06L]
D1  BZB984-C12,115  [SOTFL50P160X60-3L]
L6  1.0mH  [INDC2520X10N]
LED1  LED RGB  [LED_RGB_0603]
LED2  LED RGB  [LED_RGB_0603]
P1  Socket 2x5, Angled  [SOCKET_ANG_2x5_TH-1.27mm]
P2  Pin List 1x3  [LIST_1x3-NC]
Q3  RV2C010UNT2L  [DFN65P100X40-3L]
R11  390R  [RESC0603X03L_C]
R12  2k2  [RESC0603X03L_C]
R13  1k2  [RESC0603X03L_C]
R14  390R  [RESC0603X03L_C]
R15  2k2  [RESC0603X03L_C]
R16  1k2  [RESC0603X03L_C]
R17  100k  [RESC0603X03L_C]
R19  0R  [RESC0603X03L_C]
SB1  Solderbridge  [Solderbridge_Shorted_Power]  (value not drawn)  (net tie, no BOM)
SW1  PB SW  [KLS-TS3402]  (value not drawn)
SW2  PB SW  [SW_TACTILE_2.6x3.0MM_4-LEAD]  (value not drawn)
SW3  PB SW  [SW_TACTILE_2.6x3.0MM_4-LEAD]  (value not drawn)
TP6  Ø1.5mm,SMD  [TP_SMD_D1.5mm]  (value not drawn)  (no BOM)
TP7  Ø1.5mm,SMD  [TP_SMD_D1.5mm]  (value not drawn)  (no BOM)
TP12  Ø1.0mm,SMD  [TP_SMD_D1.0mm]  (value not drawn)  (no BOM)
TP13  Ø1.0mm,SMD  [TP_SMD_D1.0mm]  (value not drawn)  (no BOM)
U8  MX25R6435F  [SON80P300X60_HS-9N]

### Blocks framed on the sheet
LEDs: LED1 LED2 R11-R16
Debug Connector: P1 TP12 TP13
Buttons: R19 SW1-SW3
Flash memory: C38 R17 U8
Buzzer: Bz1 D1 L6 Q3
Battery and current-measurement: Bat1 C39 P2 SB1 TP6 TP7

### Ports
BUTTONS (harness BUTTON), BUZZER (in), LED1 (harness LED), LED2 (harness LED), QSPI (harness QSPI), RST_BUTTON (out), SWD (harness SWD), VDD, VDD_BZR, VDD_DBG, VDD_LED, VDD_MEM

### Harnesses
QSPI: ~{CS}, IO0, CLK, IO1, IO2, IO3
LED: GREEN, RED, BLUE
SWD: SWDIO, SWDCLK, SWO, RESET
BUTTON: BTN2, BTN1

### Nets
GND: Bat1.2 C38.2 C39.1 P1.3 P1.5 P1.9 P2.3 Q3.2(S) SW1.1(N.O) SW2.2(COM) SW3.1(N.O) TP7.1 TP13.1 U8.4(GND) U8.9(GND)
P0.00: SW1.2(COM) ; port BUTTONS.BTN1
P0.01: R19.2 ; port BUTTONS.BTN2
P0.02: R16.1 ; port LED2.RED
P0.04: R15.1 ; port LED2.GREEN
P1.13: Q3.1(G) ; port BUZZER
P2.00: U8.7(SIO3/~{RESET}) ; port QSPI.IO3
P2.01: U8.6(SCLK) ; port QSPI.CLK
P2.02: U8.5(SIO0/SI) ; port QSPI.IO0
P2.03: U8.3(SIO2/~{WP}) ; port QSPI.IO2
P2.04: U8.2(SIO1/SO) ; port QSPI.IO1
P2.05: R17.1 U8.1(~{CS}) ; port QSPI.~{CS}
P2.07: P1.6 R14.1 ; port SWD.SWO, port LED2.BLUE
P2.08: R13.1 ; port LED1.RED
P2.09: R11.1 ; port LED1.BLUE
P2.10: R12.1 ; port LED1.GREEN
RESET: P1.10 SW3.2(COM) TP12.1 ; port RST_BUTTON, port SWD.RESET
SWDCLK: P1.4 ; port SWD.SWDCLK
SWDIO: P1.2 ; port SWD.SWDIO
VBAT: Bat1.1 C39.2 P2.1 SB1.1 TP6.1
VDD: Bz1.1 C38.1 D1.1(K1) L6.2 LED1.4(A) LED2.4(A) P1.1 P2.2 R17.2 SB1.2 U8.8(VCC) ; port VDD_MEM, port VDD_LED, port VDD_DBG, port VDD_BZR, port VDD
NetBz1_2: Bz1.2 D1.2(K2) L6.1 Q3.3(D)
NetLED1_1: LED1.1(C_RED) R13.2
NetLED1_2: LED1.2(C_GREEN) R12.2
NetLED1_3: LED1.3(C_BLUE) R11.2
NetLED2_1: LED2.1(C_RED) R16.2
NetLED2_2: LED2.2(C_GREEN) R15.2
NetLED2_3: LED2.3(C_BLUE) R14.2
NetR19_1: R19.1 SW2.1(N.O)

Not connected (* = marked no-connect by the designer): D1 3(CA); P1 7 8

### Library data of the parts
Bat1 = Bat Holder L-KLS5-CR2032-23-BR: Bat Holder CR2032 SMD; Manufacturer: KLS Electronic; Part number NEMS: 100500651; Component Status: Active; Pad Count: 2; Artikkelnr Noca: N.A.; System: Connector
Bz1 = PKMCS0909E4000-R1: Piezo Buzzer, SMD, 9.0mm x 9.0mm x 1.9mm, 4kHz, 65dB @ 1.5V, <12.5Vp-p; Manufacturer: Murata; Part number NEMS: 101000026; Component Status: Active; Pad Count: 2; Note: 1.5 ~ 12.5V; Artikkelnr Noca: N.A.
C38 = C0201-100n: as C4 on sheet pca20072_nrf54l15
C39 = C0603-47µ: Capacitor, X5R, ±20%, 6.3V; Manufacturer: N.A.; Part number IPS: 00000001818; Part number NEMS: 100200277; Component Status: Active; Pad Count: 2
D1 = BZB984-C12,115: Zener Diode Array, 1 Pair, Common Anode, 12V, 265mW, ±5%; Manufacturer: Nexperia; Part number NEMS: 101300214; Component Status: Active; Pad Count: 3; Note: N.A.
L6 = L1008-1m0-15mA-24Ω-LSQBA251818T102K: Inductor, 15mA, ±10%, 24Ω; Manufacturer: Taiyo Yuden; Part number NEMS: 100300509; Component Status: Active; Pad Count: 2; Note: -40°C ~ 105°C; Artikkelnr Noca: N.A.
LED1 LED2 = APHF1608LSEEQBDZGKC: RGB LED 1.60 mm x 0.80 mm SMD; Manufacturer: Kingbright Company LLC; Part number IPS: 00000001254; Part number Norautron: 26470023; Part number NEMS: 101400123; Note: N.A.; Pad Count: 4; Component Status: Active
P1 = Socket 2x5, 1.27mm, Right Angle, TH: Socket 2x5, 1.27mm (50mil), Right Angle, TH; Manufacturer: WCON; Manufacturer Part Number: 2344-205RS0CUNR3; Part number NEMS: 100500894; Note: (Replaced 2344-205RS0CUNR1); Artikkelnr Noca: N.A.; Pad Count: 10; Component Status: Active; System: Connector
P2 = Pin List 1x3, N.C.: Pin List 1x3, 2.54mm (100mil); Manufacturer: N.A.; Part number NEMS: 100500305; Component Status: Active; Pad Count: 3; Assembly: Not mounted; System: Connector
Q3 = RV2C010UNT2L: as Q2 on sheet pca20072_sensors
R11 R14 = R0201-390: Resistor, ±1%, 0.05W; Manufacturer: N.A.; Part number IPS: 00000001258; Part number Norautron: 26470031; Part number NEMS: 100100035; Note: Chip Res 1%; Pad Count: 2; Component Status: Active
R12 R15 = R0201-2k2: Resistor, ±1%, 0.05W; Manufacturer: N.A.; Part number IPS: 00000001257; Part number Norautron: 26470030; Part number NEMS: 100100052; Note: Chip Res 1%; Pad Count: 2; Component Status: Active
R13 R16 = R0201-1k2: Resistor, ±1%, 0.05W; Manufacturer: N.A.; Part number IPS: 00000001256; Part number Norautron: 26107084; Part number NEMS: 100100045; Note: Chip Res 1%; Pad Count: 2; Component Status: Active
R17 = R0201-100k: Resistor, ±1%, 0.05W; Manufacturer: N.A.; Part number IPS: 00000001419; Part number Norautron: 26108487; Part number NEMS: 100100080; Note: Chip Res 1%; Pad Count: 2; Component Status: Active
R19 = R0201-0R: Resistor, ±5%, 0.05W; Manufacturer: N.A.; Part number IPS: 00000003245; Part number NEMS: 100100001; Note: Chip Res 5%; Pad Count: 2; Component Status: Active
SB1 = Solderbridge Shorted Power: Shorted Solderbridge Power; Manufacturer: N.A.; Part number NEMS: 100500460; Pad Count: 2; Component Status: Active; System: Connector
SW1 = L-KLS7-TS3402-2.5-250-B-T: Tactile Switch, SPNO, SMD, 260gf, 4.2x3.3x2.5mm; Manufacturer: KLS Electronic; Part number NEMS: 101500152; Note: N.A.; Pad Count: 4; Component Status: Active
SW2 SW3 = KMT021 NGJ LHS: Nano-Miniature Top Actuated Tact Switch with extended life 3.0x2.6mm; Manufacturer: C&K; Part number IPS: 00000005416; Part number NEMS: 101500039; Note: N.A.; Pad Count: 4; Component Status: Active
TP6 TP7 = TP_SMD_Ø1.5MM: as TP1 on sheet pca20072_nrf54l15
TP12 TP13 = TP_SMD_Ø1.0MM: 1.0mm circular SMD testpad; Manufacturer: Nordic Semiconductor; Manufacturer Part Number: N.A.; Part number NEMS: 100500475; Component Status: Active; Pad Count: 1
U8 = MX25R6435FZBIH3: Ultra low power, 64M-bit, serial multi I/O flash memory; Manufacturer: Macronix; Part number NEMS: 101900860; Note: N.A.; Pad Count: 8; Component Status: Active

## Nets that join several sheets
GND: pca20072_nrf54l15 (22 pins), pca20072_rffe (12 pins), pca20072_sensors (18 pins), pca20072_misc (15 pins)
P0.00: pca20072_nrf54l15 (U1.23), pca20072_misc (SW1.2)
P0.01: pca20072_nrf54l15 (0.01.1 U1.24), pca20072_misc (R19.2)
P0.02: pca20072_nrf54l15 (0.02.1 U1.27), pca20072_misc (R16.1)
P0.03: pca20072_nrf54l15 (U1.28), pca20072_sensors (U5.5)
P0.04: pca20072_nrf54l15 (0.04.1 U1.29), pca20072_misc (R15.1)
P1.04: pca20072_nrf54l15 (U1.5), pca20072_sensors (U4.4)
P1.05: pca20072_nrf54l15 (U1.6), pca20072_sensors (U4.1)
P1.06: pca20072_nrf54l15 (U1.7), pca20072_sensors (U4.14)
P1.07: pca20072_nrf54l15 (U1.8), pca20072_sensors (U4.12)
P1.08: pca20072_nrf54l15 (U1.9), pca20072_sensors (U4.13)
P1.09: pca20072_nrf54l15 (U1.37), pca20072_rffe (R8.2 U6.1)
P1.10: pca20072_nrf54l15 (U1.38), pca20072_rffe (R9.2 U6.3)
P1.11: pca20072_nrf54l15 (1.11.1 U1.39), pca20072_sensors (R3.1 U3.4 U5.4)
P1.12: pca20072_nrf54l15 (1.12.1 U1.40), pca20072_sensors (R2.1 U3.3 U5.2)
P1.13: pca20072_nrf54l15 (1.13.1 U1.41), pca20072_misc (Q3.1)
P1.14: pca20072_nrf54l15 (1.14.1 U1.42), pca20072_sensors (Q1.E R4.2)
P2.00: pca20072_nrf54l15 (U1.11), pca20072_misc (U8.7)
P2.01: pca20072_nrf54l15 (U1.12), pca20072_misc (U8.6)
P2.02: pca20072_nrf54l15 (U1.13), pca20072_misc (U8.5)
P2.03: pca20072_nrf54l15 (U1.14), pca20072_misc (U8.3)
P2.04: pca20072_nrf54l15 (U1.15), pca20072_misc (U8.2)
P2.05: pca20072_nrf54l15 (2.05.1 U1.16), pca20072_misc (R17.1 U8.1)
P2.06: pca20072_nrf54l15 (2.06.1 U1.17), pca20072_sensors (Q2.1)
P2.07: pca20072_nrf54l15 (2.07.1 U1.18), pca20072_misc (P1.6 R14.1)
P2.08: pca20072_nrf54l15 (U1.19), pca20072_misc (R13.1)
P2.09: pca20072_nrf54l15 (U1.20), pca20072_misc (R11.1)
P2.10: pca20072_nrf54l15 (U1.21), pca20072_misc (R12.1)
RESET: pca20072_nrf54l15 (R1.2 TP3.1), pca20072_misc (P1.10 SW3.2 TP12.1)
RF: pca20072_nrf54l15 (C11.2 L4.2), pca20072_rffe (C28.2)
SWDCLK: pca20072_nrf54l15 (TP4.1 U1.26), pca20072_misc (P1.4)
SWDIO: pca20072_nrf54l15 (TP5.1 U1.25), pca20072_misc (P1.2)
VDD: pca20072_nrf54l15 (12 pins), pca20072_sensors (16 pins), pca20072_misc (11 pins)

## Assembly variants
Full: not fitted C17 C19 C27 C31 P2
Release: not fitted Bz500 C17 C19 C27 C31 C500 D500 L500 LED2 P2 Q300 Q304 Q500 R303 R503 R504 R505 R506 R508 SW501 SW502 U500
